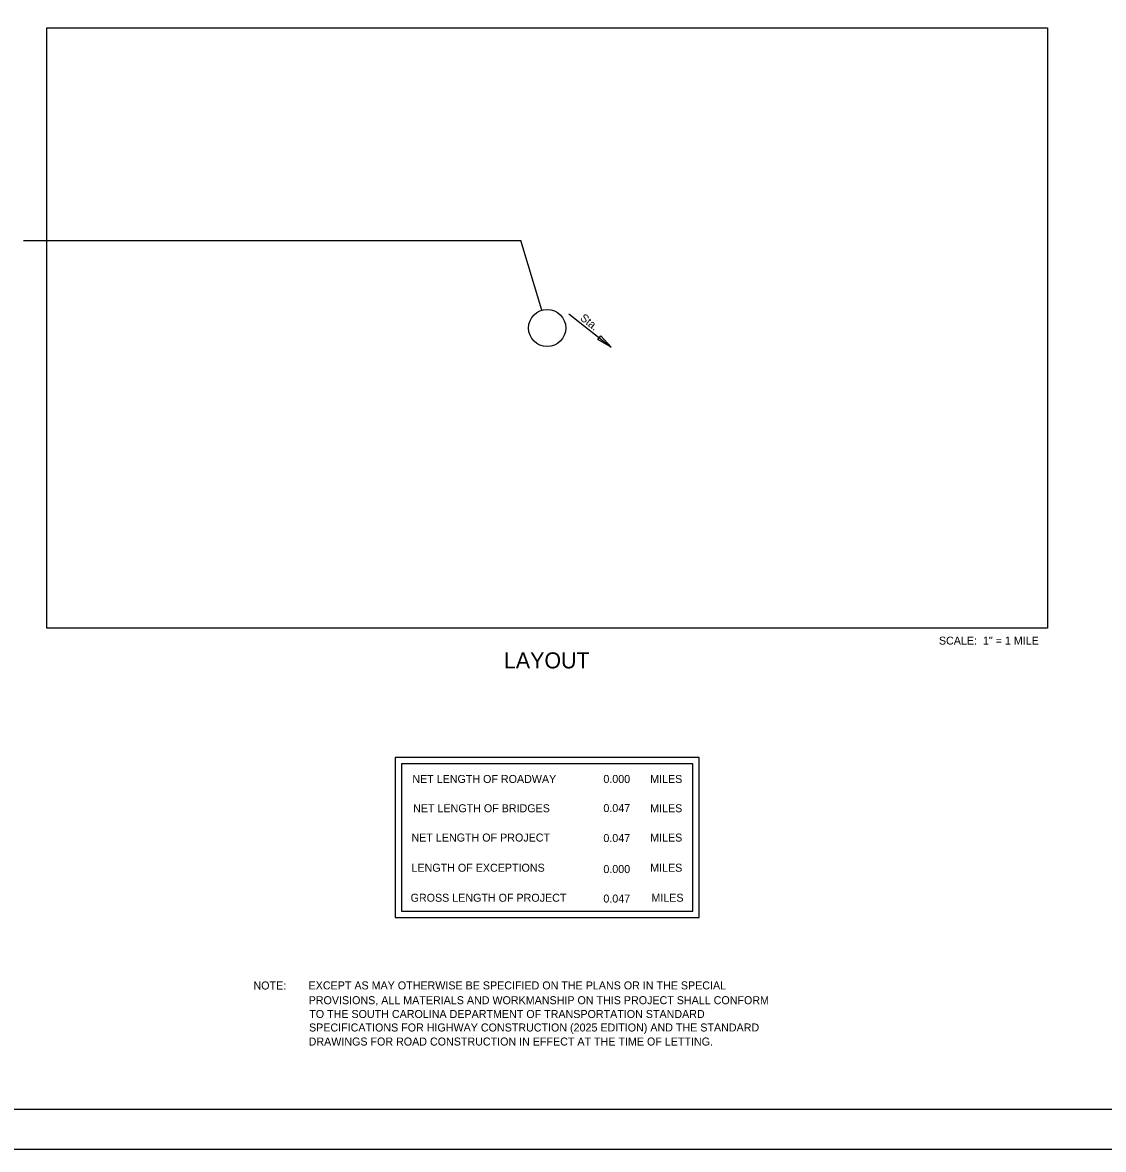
# Model space of a CAD drawing. Extents: x 291 to 2091, y 224 to 1324.
# Drawn here: x 892 to 1567, y 224 to 928 of the extents above; entities that cross this region are included whole.
import ezdxf

# ---------------------------------------------------------------- set-up
doc = ezdxf.new("R2010")
doc.units = 0
for name, color, linetype in [('BR_BORDER LINES', 7, 'Continuous'), ('BR_REBAR', 7, 'Continuous'), ('BR_TEXT', 7, 'Continuous'), ('Default', 7, 'Continuous'), ('RD_SHT_IplotShp', 7, 'Continuous')]:
    doc.layers.add(name, color=color, linetype=linetype)

msp = doc.modelspace()

# ---------------------------------------------------------------- linework, layer by layer
at = {"layer": 'BR_BORDER LINES'}
msp.add_line((391.1, 249.11), (2066.1, 249.11), dxfattribs=at)
at = {"layer": 'BR_REBAR'}
for p, q in [((906.87, 549.64), (906.87, 924.64)), ((906.87, 924.64), (1531.87, 924.64)), ((1531.87, 924.64), (1531.87, 549.64)), ((892.13, 791.71), (1202.92, 791.71)), ((1216.01, 748.27), (1202.92, 791.71)), ((1232.94, 745.96), (1259.3, 725.27)), ((1531.87, 549.64), (906.87, 549.64))]:
    msp.add_line(p, q, dxfattribs=at)
msp.add_lwpolyline([(1252.8, 732.16), (1259.3, 725.27), (1251.06, 729.95)], close=True, dxfattribs=at)
msp.add_circle((1219.37, 737.14), 11.62, dxfattribs=at)
at = {"layer": 'BR_TEXT'}
for points in [[(1314.37, 468.89), (1124.37, 468.89), (1124.37, 368.89), (1314.37, 368.89)], [(1310.37, 464.89), (1128.37, 464.89), (1128.37, 372.89), (1310.37, 372.89)]]:
    msp.add_lwpolyline(points, close=True, dxfattribs=at)
at = {"layer": 'Default'}
for p, q in [((906.87, 549.64), (906.87, 924.64)), ((906.87, 924.64), (1531.87, 924.64)), ((1531.87, 924.64), (1531.87, 549.64)), ((1531.87, 549.64), (906.87, 549.64))]:
    msp.add_line(p, q, dxfattribs=at)
at = {"layer": 'RD_SHT_IplotShp'}
msp.add_lwpolyline([(291.1, 1324.04), (2091.1, 1324.04), (2091.1, 224.04), (291.1, 224.04)], close=True, dxfattribs=at)

# ---------------------------------------------------------------- texts
at = {"layer": 'BR_REBAR'}
msp.add_text('Sta.', height=5, rotation=321.86505, dxfattribs=at).set_placement((1239.56, 742.59))
at = {"layer": 'BR_TEXT'}
for s, height, p in [('SCALE:  1" = 1 MILE', 5, (1464.11, 539.38)), ('LAYOUT', 10, (1192.37, 524.54)), ('NET LENGTH OF ROADWAY', 5, (1135.12, 452.97)), ('0.000', 5, (1254.49, 452.97)), ('MILES', 5, (1283.73, 452.97)), ('NET LENGTH OF BRIDGES', 5, (1135.62, 434.67)), ('0.047', 5, (1254.49, 434.79)), ('MILES', 5, (1283.72, 434.67)), ('NET LENGTH OF PROJECT', 5, (1134.62, 416.37)), ('0.047', 5, (1254.49, 416.06)), ('MILES', 5, (1283.72, 416.37)), ('LENGTH OF EXCEPTIONS', 5, (1134.62, 397.52)), ('0.000', 5, (1254.49, 396.69)), ('MILES', 5, (1283.74, 397.52)), ('GROSS LENGTH OF PROJECT', 5, (1134.07, 378.77)), ('0.047', 5, (1254.49, 378.28)), ('MILES', 5, (1284.49, 378.77)), ('NOTE:', 5, (1035.88, 323.96)), ('EXCEPT AS MAY OTHERWISE BE SPECIFIED ON THE PLANS OR IN THE SPECIAL ', 5.0001, (1070.33, 324.02)), ('PROVISIONS, ALL MATERIALS AND WORKMANSHIP ON THIS PROJECT SHALL CONFORM ', 5.0001, (1070.38, 314.77)), ('TO THE SOUTH CAROLINA DEPARTMENT OF TRANSPORTATION STANDARD ', 5.0001, (1070.74, 306.16)), ('SPECIFICATIONS FOR HIGHWAY CONSTRUCTION (2025 EDITION) AND THE STANDARD', 5.0001, (1070.59, 297.73)), ('DRAWINGS FOR ROAD CONSTRUCTION IN EFFECT AT THE TIME OF LETTING.', 5.0001, (1070.36, 288.95))]:
    msp.add_text(s, height=height, dxfattribs=at).set_placement(p)

doc.saveas('drawing.dxf')
